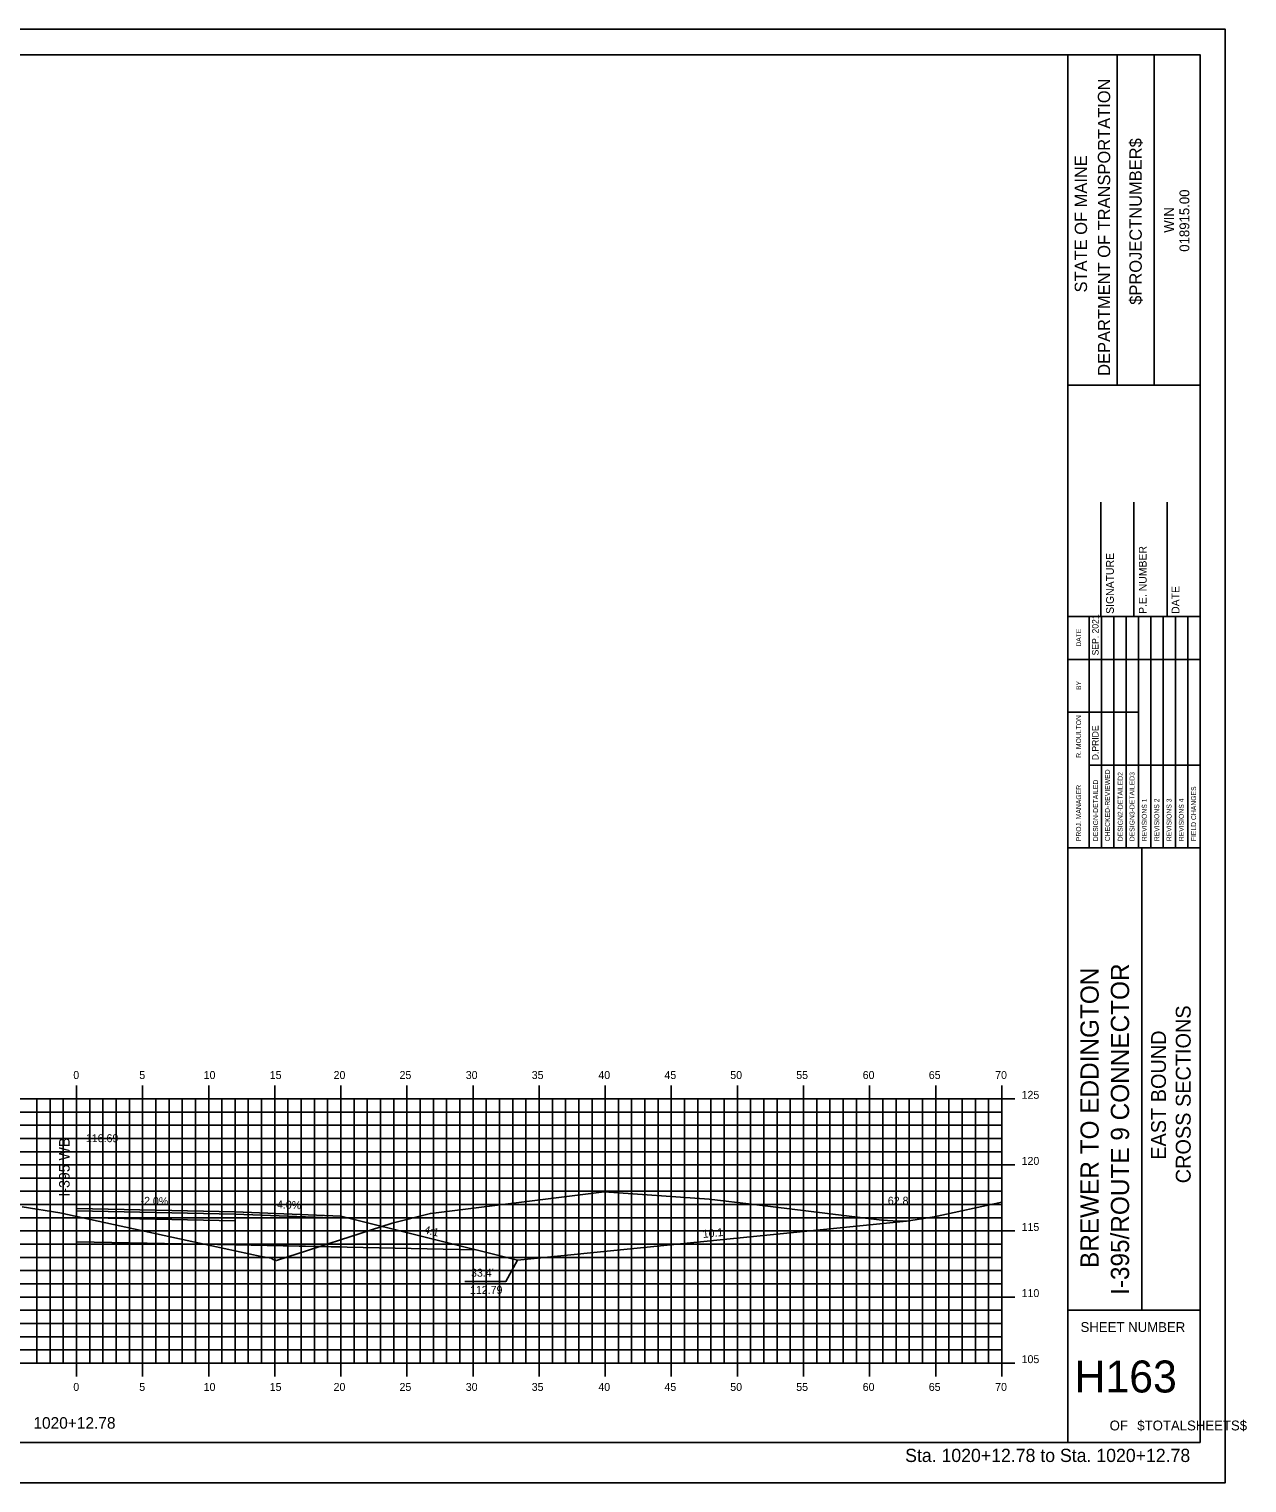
# Model space of a CAD drawing. Extents: x 853956 to 854128, y 365624 to 365734.
# Drawn here: x 854035.5 to 854127.6, y 365624 to 365734 of the extents above; entities that cross this region are included whole.
import ezdxf

# ---------------------------------------------------------------- set-up
doc = ezdxf.new("R2010")
doc.units = 0
for name, color, linetype in [('ANNOTATION', 7, 'Continuous'), ('BORDER', 7, 'Continuous'), ('D_Roadway_Centerline', 7, 'Continuous'), ('D_Roadway_Centerline_Text', 7, 'Continuous'), ('D_Roadway_Edge_Shoulder', 7, 'Continuous'), ('D_Roadway_Edge_TW', 7, 'Continuous'), ('D_Roadway_SubGrade', 7, 'Continuous'), ('D_Text_Standard', 7, 'Continuous'), ('H_V ANNOTATION', 7, 'Continuous'), ('MAJOR', 7, 'Continuous'), ('MINOR', 7, 'Continuous'), ('PLOT BOUNDARY', 7, 'Continuous'), ('S_Roadway_Centerline', 7, 'Continuous')]:
    doc.layers.add(name, color=color, linetype=linetype)

msp = doc.modelspace()

# ---------------------------------------------------------------- linework, layer by layer
at = {"layer": 'ANNOTATION'}
msp.add_lwpolyline([(854068.47, 365639.21), (854071.58, 365639.21), (854072.45, 365640.82)], dxfattribs=at)
at = {"layer": 'BORDER'}
for p, q in [((854114.09, 365627.03), (854114.09, 365732.03)), ((854117.82, 365707.02), (854117.82, 365732.02)), ((854120.61, 365707.02), (854120.61, 365732.02)), ((854114.09, 365707.02), (854124.09, 365707.02)), ((854116.59, 365689.53), (854116.59, 365698.18)), ((854119.09, 365689.53), (854119.09, 365698.18)), ((854121.59, 365689.53), (854121.59, 365698.18)), ((854114.09, 365689.53), (854124.09, 365689.53)), ((854114.09, 365672.03), (854124.09, 365672.03)), ((854119.68, 365637.03), (854119.68, 365672.03)), ((854114.09, 365637.03), (854124.09, 365637.03))]:
    msp.add_line(p, q, dxfattribs=at)
msp.add_lwpolyline([(853964.09, 365627.03), (854124.09, 365627.03), (854124.09, 365732.03), (853964.09, 365732.03)], close=True, dxfattribs=at)
for points in [[(854115.7, 365686.28), (854115.7, 365689.53)], [(854116.64, 365672.03), (854116.64, 365689.53)], [(854117.57, 365689.53), (854117.57, 365672.03)], [(854118.5, 365672.03), (854118.5, 365689.53)], [(854119.43, 365672.03), (854119.43, 365689.53)], [(854120.36, 365672.03), (854120.36, 365689.53)], [(854121.29, 365672.03), (854121.29, 365689.53)], [(854122.23, 365672.03), (854122.23, 365689.53)], [(854123.16, 365672.03), (854123.16, 365689.53)], [(854115.7, 365672.03), (854115.7, 365688.82)], [(854114.09, 365686.28), (854124.09, 365686.28)], [(854114.09, 365682.28), (854115.7, 365682.28)], [(854115.7, 365682.28), (854119.43, 365682.28)], [(854115.7, 365678.28), (854124.09, 365678.28)]]:
    msp.add_lwpolyline(points, dxfattribs=at)
at = {"layer": 'D_Roadway_Centerline'}
for p, q in [((854072.45, 365640.82), (854101.87, 365643.77)), ((854051.09, 365641.98), (854069.26, 365641.61))]:
    msp.add_line(p, q, dxfattribs=at)
msp.add_lwpolyline([(854059.09, 365644.16), (854072.45, 365640.82)], dxfattribs=at)
at = {"layer": 'D_Roadway_Edge_Shoulder'}
msp.add_lwpolyline([(854051.09, 365644.48), (854059.09, 365644.16), (854059.09, 365643.99), (854051.09, 365644.31)], close=True, dxfattribs=at)
at = {"layer": 'D_Roadway_Edge_TW'}
msp.add_lwpolyline([(854039.09, 365644.72), (854051.09, 365644.48), (854051.09, 365644.31), (854039.09, 365644.55)], close=True, dxfattribs=at)
at = {"layer": 'D_Roadway_SubGrade'}
msp.add_line((854039.08, 365650.62), (854039.08, 365642.22), dxfattribs=at)
for points in [[(854039.09, 365644.05), (854051.09, 365643.81), (854051.09, 365641.98), (854039.09, 365642.22)], [(854051.09, 365643.81), (854051.09, 365644.31), (854059.09, 365643.99), (854059.09, 365644.16), (854059.09, 365641.82), (854051.09, 365641.98)]]:
    msp.add_lwpolyline(points, close=True, dxfattribs=at)
at = {"layer": 'MAJOR'}
for p, q in [((854039.09, 365654.03), (854039.09, 365653.03)), ((854044.09, 365654.03), (854044.09, 365653.03)), ((854049.09, 365654.03), (854049.09, 365653.03)), ((854054.09, 365654.03), (854054.09, 365653.03)), ((854059.09, 365654.03), (854059.09, 365653.03)), ((854064.09, 365654.03), (854064.09, 365653.03)), ((854069.09, 365654.03), (854069.09, 365653.03)), ((854074.09, 365654.03), (854074.09, 365653.03)), ((854079.09, 365654.03), (854079.09, 365653.03)), ((854084.09, 365654.03), (854084.09, 365653.03)), ((854089.09, 365654.03), (854089.09, 365653.03)), ((854094.09, 365654.03), (854094.09, 365653.03)), ((854099.09, 365654.03), (854099.09, 365653.03)), ((854104.09, 365654.03), (854104.09, 365653.03)), ((854109.09, 365654.03), (854109.09, 365653.03)), ((853969.09, 365653.03), (854109.09, 365653.03)), ((853969.09, 365653.03), (854109.09, 365653.03)), ((854039.09, 365633.03), (854039.09, 365653.03)), ((854044.09, 365633.03), (854044.09, 365653.03)), ((854049.09, 365633.03), (854049.09, 365653.03)), ((854054.09, 365633.03), (854054.09, 365653.03)), ((854059.09, 365633.03), (854059.09, 365653.03)), ((854064.09, 365633.03), (854064.09, 365653.03)), ((854069.09, 365633.03), (854069.09, 365653.03)), ((854074.09, 365633.03), (854074.09, 365653.03)), ((854079.09, 365633.03), (854079.09, 365653.03)), ((854084.09, 365633.03), (854084.09, 365653.03)), ((854089.09, 365633.03), (854089.09, 365653.03)), ((854094.09, 365633.03), (854094.09, 365653.03)), ((854099.09, 365633.03), (854099.09, 365653.03)), ((854104.09, 365633.03), (854104.09, 365653.03)), ((854110.09, 365653.03), (854108.09, 365653.03)), ((854109.09, 365633.03), (854109.09, 365653.03)), ((854109.09, 365633.03), (854109.09, 365653.03)), ((853969.09, 365648.03), (854109.09, 365648.03)), ((854110.09, 365648.03), (854108.09, 365648.03)), ((853969.09, 365643.03), (854109.09, 365643.03)), ((854110.09, 365643.03), (854108.09, 365643.03)), ((853969.09, 365638.03), (854109.09, 365638.03)), ((854110.09, 365638.03), (854108.09, 365638.03)), ((853969.09, 365633.03), (854109.09, 365633.03)), ((853969.09, 365633.03), (854109.09, 365633.03)), ((854039.09, 365632.02), (854039.09, 365633.03)), ((854044.09, 365632.02), (854044.09, 365633.03)), ((854049.09, 365632.02), (854049.09, 365633.03)), ((854054.09, 365632.02), (854054.09, 365633.03)), ((854059.09, 365632.02), (854059.09, 365633.03)), ((854064.09, 365632.02), (854064.09, 365633.03)), ((854069.09, 365632.02), (854069.09, 365633.03)), ((854074.09, 365632.02), (854074.09, 365633.03)), ((854079.09, 365632.02), (854079.09, 365633.03)), ((854084.09, 365632.02), (854084.09, 365633.03)), ((854089.09, 365632.02), (854089.09, 365633.03)), ((854094.09, 365632.02), (854094.09, 365633.03)), ((854099.09, 365632.02), (854099.09, 365633.03)), ((854104.09, 365632.02), (854104.09, 365633.03)), ((854110.09, 365633.03), (854108.09, 365633.03)), ((854109.09, 365632.02), (854109.09, 365633.03))]:
    msp.add_line(p, q, dxfattribs=at)
at = {"layer": 'MINOR'}
for p, q in [((854036.09, 365633.03), (854036.09, 365653.03)), ((854037.09, 365633.03), (854037.09, 365653.03)), ((854038.09, 365633.03), (854038.09, 365653.03)), ((854040.09, 365633.03), (854040.09, 365653.03)), ((854041.09, 365633.03), (854041.09, 365653.03)), ((854042.09, 365633.03), (854042.09, 365653.03)), ((854043.09, 365633.03), (854043.09, 365653.03)), ((854045.09, 365633.03), (854045.09, 365653.03)), ((854046.09, 365633.03), (854046.09, 365653.03)), ((854047.09, 365633.03), (854047.09, 365653.03)), ((854048.09, 365633.03), (854048.09, 365653.03)), ((854050.09, 365633.03), (854050.09, 365653.03)), ((854051.09, 365633.03), (854051.09, 365653.03)), ((854052.09, 365633.03), (854052.09, 365653.03)), ((854053.09, 365633.03), (854053.09, 365653.03)), ((854055.09, 365633.03), (854055.09, 365653.03)), ((854056.09, 365633.03), (854056.09, 365653.03)), ((854057.09, 365633.03), (854057.09, 365653.03)), ((854058.09, 365633.03), (854058.09, 365653.03)), ((854060.09, 365633.03), (854060.09, 365653.03)), ((854061.09, 365633.03), (854061.09, 365653.03)), ((854062.09, 365633.03), (854062.09, 365653.03)), ((854063.09, 365633.03), (854063.09, 365653.03)), ((854065.09, 365633.03), (854065.09, 365653.03)), ((854066.09, 365633.03), (854066.09, 365653.03)), ((854067.09, 365633.03), (854067.09, 365653.03)), ((854068.09, 365633.03), (854068.09, 365653.03)), ((854070.09, 365633.03), (854070.09, 365653.03)), ((854071.09, 365633.03), (854071.09, 365653.03)), ((854072.09, 365633.03), (854072.09, 365653.03)), ((854073.09, 365633.03), (854073.09, 365653.03)), ((854075.09, 365633.03), (854075.09, 365653.03)), ((854076.09, 365633.03), (854076.09, 365653.03)), ((854077.09, 365633.03), (854077.09, 365653.03)), ((854078.09, 365633.03), (854078.09, 365653.03)), ((854080.09, 365633.03), (854080.09, 365653.03)), ((854081.09, 365633.03), (854081.09, 365653.03)), ((854082.09, 365633.03), (854082.09, 365653.03)), ((854083.09, 365633.03), (854083.09, 365653.03)), ((854085.09, 365633.03), (854085.09, 365653.03)), ((854086.09, 365633.03), (854086.09, 365653.03)), ((854087.09, 365633.03), (854087.09, 365653.03)), ((854088.09, 365633.03), (854088.09, 365653.03)), ((854090.09, 365633.03), (854090.09, 365653.03)), ((854091.09, 365633.03), (854091.09, 365653.03)), ((854092.09, 365633.03), (854092.09, 365653.03)), ((854093.09, 365633.03), (854093.09, 365653.03)), ((854095.09, 365633.03), (854095.09, 365653.03)), ((854096.09, 365633.03), (854096.09, 365653.03)), ((854097.09, 365633.03), (854097.09, 365653.03)), ((854098.09, 365633.03), (854098.09, 365653.03)), ((854100.09, 365633.03), (854100.09, 365653.03)), ((854101.09, 365633.03), (854101.09, 365653.03)), ((854102.09, 365633.03), (854102.09, 365653.03)), ((854103.09, 365633.03), (854103.09, 365653.03)), ((854105.09, 365633.03), (854105.09, 365653.03)), ((854106.09, 365633.03), (854106.09, 365653.03)), ((854107.09, 365633.03), (854107.09, 365653.03)), ((854108.09, 365633.03), (854108.09, 365653.03)), ((853969.09, 365652.03), (854109.09, 365652.03)), ((853969.09, 365651.03), (854109.09, 365651.03)), ((854109.09, 365652.03), (854108.09, 365652.03)), ((854109.09, 365651.03), (854108.09, 365651.03)), ((853969.09, 365650.03), (854109.09, 365650.03)), ((854109.09, 365650.03), (854108.09, 365650.03)), ((853969.09, 365649.03), (854109.09, 365649.03)), ((854109.09, 365649.03), (854108.09, 365649.03)), ((853969.09, 365647.03), (854109.09, 365647.03)), ((854109.09, 365647.03), (854108.09, 365647.03)), ((853969.09, 365646.03), (854109.09, 365646.03)), ((854109.09, 365646.03), (854108.09, 365646.03)), ((853969.09, 365645.03), (854109.09, 365645.03)), ((854109.09, 365645.03), (854108.09, 365645.03)), ((853969.09, 365644.03), (854109.09, 365644.03)), ((854109.09, 365644.03), (854108.09, 365644.03)), ((853969.09, 365642.03), (854109.09, 365642.03)), ((854109.09, 365642.03), (854108.09, 365642.03)), ((853969.09, 365641.03), (854109.09, 365641.03)), ((853969.09, 365640.03), (854109.09, 365640.03)), ((854109.09, 365641.03), (854108.09, 365641.03)), ((854109.09, 365640.03), (854108.09, 365640.03)), ((853969.09, 365639.03), (854109.09, 365639.03)), ((854109.09, 365639.03), (854108.09, 365639.03)), ((853969.09, 365637.03), (854109.09, 365637.03)), ((854109.09, 365637.03), (854108.09, 365637.03)), ((853969.09, 365636.03), (854109.09, 365636.03)), ((854109.09, 365636.03), (854108.09, 365636.03)), ((853969.09, 365635.03), (854109.09, 365635.03)), ((854109.09, 365635.03), (854108.09, 365635.03)), ((853969.09, 365634.03), (854109.09, 365634.03)), ((854109.09, 365634.03), (854108.09, 365634.03))]:
    msp.add_line(p, q, dxfattribs=at)
at = {"layer": 'PLOT BOUNDARY'}
msp.add_lwpolyline([(853955.99, 365623.97), (854125.99, 365623.97), (854125.99, 365733.97), (853955.99, 365733.97)], close=True, dxfattribs=at)
at = {"layer": 'S_Roadway_Centerline'}
msp.add_lwpolyline([(854034.97, 365644.85), (854037.82, 365644.41), (854047.46, 365642.32), (854053.05, 365641.09), (854053.83, 365640.98), (854053.96, 365640.86), (854054.21, 365640.79), (854062.98, 365643.63), (854065.87, 365644.36), (854066.49, 365644.42), (854079.02, 365646), (854086.96, 365645.43), (854090.35, 365645.04), (854100.01, 365643.86), (854101.27, 365643.76), (854101.87, 365643.77), (854103.98, 365644.11), (854109.09, 365645.2)], dxfattribs=at)

# ---------------------------------------------------------------- texts
at = {"layer": 'ANNOTATION'}
for s, height, rotation, p in [('I-395 WB', 0.8, 90, (854038.57, 365645.63)), ('-2.0%', 0.6, 358.8543, (854043.93, 365645.02)), ('-4.0%', 0.6, 357.7093, (854053.98, 365644.76)), ('4:1', 0.6, 345.9638, (854065.34, 365642.87)), ('10:1', 0.6, 5.7363, (854086.49, 365642.5)), ("33.4' ", 0.6, 360, (854068.94, 365639.57)), ('112.79', 0.6, 360, (854068.86, 365638.27))]:
    msp.add_text(s, height=height, rotation=rotation, dxfattribs=at).set_placement(p)
at = {"layer": 'BORDER'}
for s, height, p in [('DEPARTMENT OF TRANSPORTATION', 0.9318, (854117.29, 365707.73)), ('$PROJECTNUMBER$', 0.9318, (854119.68, 365713.11)), ('STATE OF MAINE', 0.9318, (854115.54, 365714.04)), ('018915.00', 0.745, (854123.28, 365717.12)), ('WIN', 0.745, (854122.12, 365718.56)), ('SIGNATURE', 0.591, (854117.57, 365689.72)), ('P.E. NUMBER', 0.5906, (854120.05, 365689.72)), ('DATE', 0.591, (854122.53, 365689.72)), ('SEP. 2021', 0.485, (854116.41, 365686.58)), ('DATE', 0.371, (854115.09, 365687.24)), ('BY', 0.371, (854115.09, 365683.96)), ('R. MOULTON', 0.373, (854115.09, 365678.83)), ('D.PRIDE', 0.485, (854116.41, 365678.65)), ('CHECKED-REVIEWED', 0.3727, (854117.27, 365672.52)), ('DESIGN2-DETAILED2', 0.3727, (854118.24, 365672.52)), ('DESIGN3-DETAILED3', 0.3727, (854119.13, 365672.52)), ('PROJ. MANAGER', 0.3727, (854115.09, 365672.52)), ('DESIGN-DETAILED', 0.3727, (854116.37, 365672.52)), ('FIELD CHANGES', 0.3727, (854123.79, 365672.52)), ('REVISIONS 1', 0.3727, (854120.06, 365672.52)), ('REVISIONS 2', 0.3727, (854121, 365672.52)), ('REVISIONS 3', 0.3727, (854121.93, 365672.52)), ('REVISIONS 4', 0.3727, (854122.86, 365672.52)), ('I-395/ROUTE 9 CONNECTOR', 1.3779, (854118.72, 365638.19)), ('BREWER TO EDDINGTON', 1.3779, (854116.42, 365640.23)), ('CROSS SECTIONS', 1.125, (854123.38, 365646.64)), ('EAST BOUND', 1.125, (854121.51, 365648.42))]:
    msp.add_text(s, height=height, rotation=90, dxfattribs=at).set_placement(p)
for s, height, p in [('SHEET NUMBER', 0.7453, (854115.05, 365635.39)), ('H163', 2.419, (854114.6, 365630.81)), ('OF', 0.745, (854117.25, 365627.94)), ('$TOTALSHEETS$', 0.7453, (854119.34, 365627.94))]:
    msp.add_text(s, height=height, dxfattribs=at).set_placement(p)
at = {"layer": 'D_Roadway_Centerline_Text'}
msp.add_text('116.69', height=0.6, dxfattribs=at).set_placement((854039.8, 365649.75))
at = {"layer": 'D_Text_Standard'}
msp.add_text("62.8'", height=0.6, dxfattribs=at).set_placement((854100.47, 365645.02))
at = {"layer": 'H_V ANNOTATION'}
for s, height, p in [('0', 0.6, (854038.85, 365654.53)), ('5', 0.6, (854043.84, 365654.53)), ('10', 0.6, (854048.71, 365654.53)), ('15', 0.6, (854053.71, 365654.53)), ('20', 0.6, (854058.54, 365654.53)), ('25', 0.6, (854063.53, 365654.53)), ('30', 0.6, (854068.54, 365654.53)), ('35', 0.6, (854073.53, 365654.53)), ('40', 0.6, (854078.57, 365654.53)), ('45', 0.6, (854083.57, 365654.53)), ('50', 0.6, (854088.55, 365654.53)), ('55', 0.6, (854093.54, 365654.53)), ('60', 0.6, (854098.57, 365654.53)), ('65', 0.6, (854103.57, 365654.53)), ('70', 0.6, (854108.59, 365654.53)), ('125', 0.6, (854110.59, 365653.03)), ('120', 0.6, (854110.59, 365648.03)), ('115', 0.6, (854110.59, 365643.03)), ('110', 0.6, (854110.59, 365638.03)), ('105', 0.6, (854110.59, 365633.03)), ('0', 0.6, (854038.85, 365630.93)), ('5', 0.6, (854043.84, 365630.93)), ('10', 0.6, (854048.71, 365630.93)), ('15', 0.6, (854053.71, 365630.93)), ('20', 0.6, (854058.54, 365630.93)), ('25', 0.6, (854063.53, 365630.93)), ('30', 0.6, (854068.54, 365630.93)), ('35', 0.6, (854073.53, 365630.93)), ('40', 0.6, (854078.57, 365630.93)), ('45', 0.6, (854083.57, 365630.93)), ('50', 0.6, (854088.55, 365630.93)), ('55', 0.6, (854093.54, 365630.93)), ('60', 0.6, (854098.57, 365630.93)), ('65', 0.6, (854103.57, 365630.93)), ('70', 0.6, (854108.59, 365630.93)), ('1020+12.78', 0.875, (854035.83, 365628.07)), ('Sta. 1020+12.78 to Sta. 1020+12.78', 1.0002, (854101.78, 365625.55))]:
    msp.add_text(s, height=height, dxfattribs=at).set_placement(p)

doc.saveas('drawing.dxf')
